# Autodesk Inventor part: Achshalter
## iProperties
Created: 2003-12
Part Number: Achshalter
Material: Aluminium - 6061
Document SubType Name: Modellieren
Designer: Ulrich
Control State: 0
Master: False
Checked Out: False
Shininess: 20.0
Angle Display Precision: 2
Document Length Units: 11269
Document Angle Units: 11279
Document Time Units: 11290
Document Mass Units: 11283
Document Length Units Precision: 3
Document Angle Units Precision: 2
Density: 0.0
Volumn: 0.0
Area: 0.0
PropertySet Name: Model Information
Author: Ulrich
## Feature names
1. Grundkörper [Extrusion]
2. Distanzringe [Extrusion]
3. Bohrung_Kurbelllager [Extrusion]
4. Nut [Extrusion]
